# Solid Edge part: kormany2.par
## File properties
Author: morva
Template: iso metric part.par
Last saved by: morva
Revision: 19
Application: Solid Edge
Density: 2712.000 kg/m^3
Accuracy: 0.990
Username: morva
Material: Aluminum, 6061-T6
Face Style: Aluminum
Fill Style: ANSI38(Aluminum)
Virtual Style: Polished aluminum
Grouping: Metals\Aluminium Alloys
LibraryName: Materials
Coef. of Thermal Exp: 2.3e-05
Thermal Conductivity: 180.0
Specific Heat: 920.0
Modulus of Elasticity: 68947570000.0
Poisson's Ratio: 0.33
Yield Stress: 275790280.0
Ultimate Stress: 310264065.0
Elongation: 0.0
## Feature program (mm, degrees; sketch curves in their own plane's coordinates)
sketch for "unnamed Protrusion 1" #1 plane through (0, 0, 0) normal (0, 0, 1) x-axis (1, 0, 0)
  circle centre (0, 0) radius 14
sketch for "unnamed Protrusion 1" #2 plane through (0, 0, 0) normal (0, 0, 1) x-axis (1, 0, 0)
  circle centre (0, 0) radius 11
extrude "unnamed Protrusion 1" add finite 500 along -normal
sketch for "ExtrudedCutout_1" plane through (0, 0, 0) normal (0, 0, 1) x-axis (1, 0, 0)
  line (-1.5, -13.9194) -> (-1.5, 13.9194)
  arc centre (0, 0) radius 14 from (-1.5, 13.9194) to (1.5, 13.9194) cw
  line (1.5, -13.9194) -> (1.5, 13.9194)
extrude "ExtrudedCutout_1" cut finite 30 along -normal
sketch for "unnamed Cutout 1" plane through (0, 0, 0) normal (0, -1, 0) x-axis (1, 0, 0)
  circle centre (0, -30) radius 3
extrude "unnamed Cutout 1" cut through
thread "Thread_1"  ThreadDepth = 50 mm
thread "Thread_2"  ThreadDepth = 15 mm
sketch for "unnamed Cutout 2" plane through (0, 0, 0) normal (1, 0, 0) x-axis (0, 1, 0)
extrude "unnamed Cutout 2" cut through along +normal
chamfer "Chamfer_1" setback 1
chamfer "Chamfer_2" setback 1
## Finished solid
Body 1: solid body, 16 faces, 32 edges, 16 vertices.
  Faces by surface: cylinder 7, plane 7, cone 2
  Edges by curve: line 16, circle 10, intersection 6
Bounding box of the edges (mm): 28.000 x 28.000 x 500.000, from (-14, -14, -500) to (14, 14, 0).
Cylindrical faces by radius (mm): R3 x2, R5 x1, R11 x2, R14 x2
Conical faces (half-angle, radius in mm at the cone's reference point): 45 deg R11 x1, 45 deg R13 x1
Planar faces by outward normal: +x 2, +z 2, -x 2, -z 1
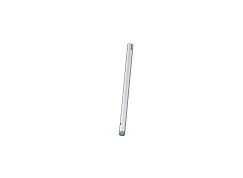
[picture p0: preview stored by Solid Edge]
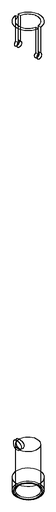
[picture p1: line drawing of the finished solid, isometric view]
